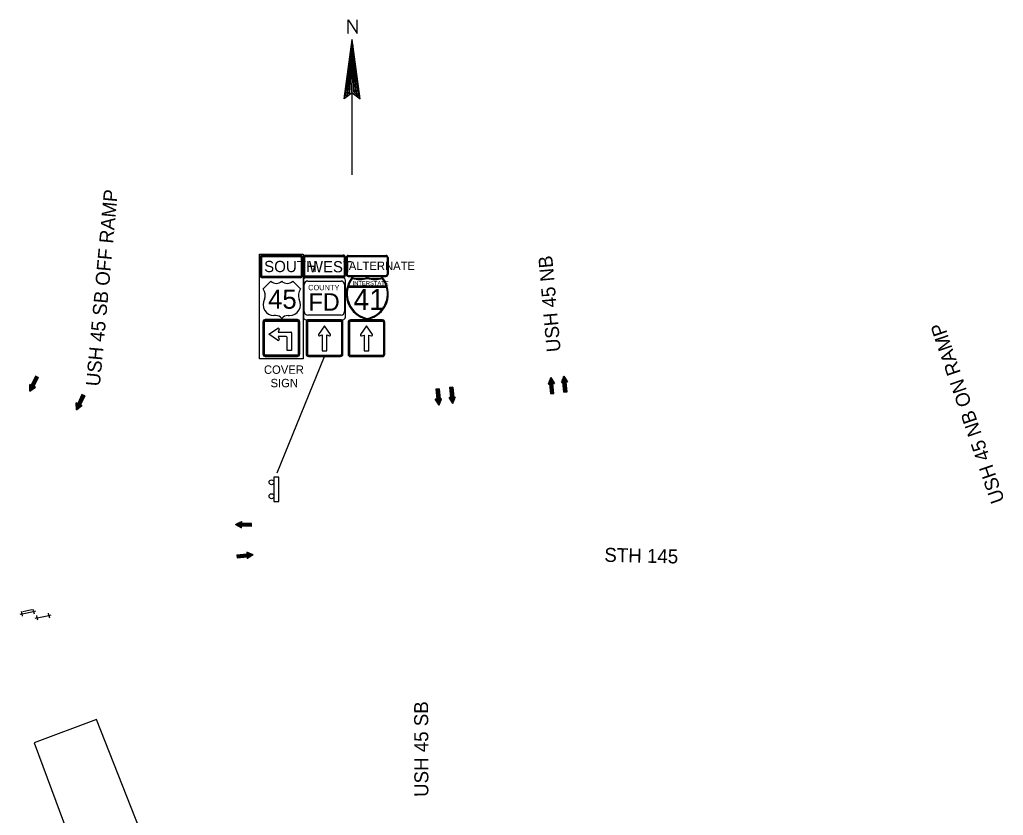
# Model space of a CAD drawing. Extents: x 358662 to 361839, y 132407 to 133741.
# Drawn here: x 361136 to 361839, y 133159 to 133727 of the extents above; entities that cross this region are included whole.
import ezdxf

# ---------------------------------------------------------------- set-up
doc = ezdxf.new("R2010")
doc.units = 0
for name, color, linetype in [('E_BLD_Dash', 7, 'Continuous'), ('E_BLD_Footing', 7, 'Continuous'), ('E_WTR_Wetland', 7, 'Continuous'), ('P_FTMS_LaneLbl', 7, 'Continuous')]:
    doc.layers.add(name, color=color, linetype=linetype)

msp = doc.modelspace()

# ---------------------------------------------------------------- linework, layer by layer
at = {"layer": 'E_BLD_Dash'}
for p, q in [((361137.32, 133302.53), (361135.66, 133302.17)), ((361137.32, 133302.53), (361136.96, 133304.19)), ((361137.32, 133302.53), (361145.63, 133304.32)), ((361137.68, 133300.87), (361137.32, 133302.53)), ((361137.94, 133304.4), (361144.29, 133305.77)), ((361145.63, 133304.32), (361145.27, 133305.99)), ((361145.63, 133304.32), (361147.29, 133304.68)), ((361145.63, 133304.32), (361145.98, 133302.66)), ((361148.26, 133299.68), (361146.6, 133299.32)), ((361148.26, 133299.68), (361147.9, 133301.34)), ((361148.26, 133299.68), (361156.57, 133301.48)), ((361148.62, 133298.02), (361148.26, 133299.68)), ((361156.57, 133301.48), (361156.21, 133303.14)), ((361156.57, 133301.48), (361158.23, 133301.84)), ((361156.57, 133301.48), (361156.93, 133299.82))]:
    msp.add_line(p, q, dxfattribs=at)
msp.add_lwpolyline([(361145.9, 133210.4), (361246.12, 132941.02), (361294.54, 132769.14), (361334.5, 132574.47), (361355.34, 132406.97), (361400.51, 132412.18), (361383.14, 132580.56), (361355.68, 132735.56), (361320.44, 132874.11), (361292.28, 132968.83), (361190.63, 133227.12)], close=True, dxfattribs=at)
at = {"layer": 'E_BLD_Footing'}
for p, q in [((361147.31, 133472.38), (361142.96, 133463.21)), ((361147.72, 133472.19), (361142.99, 133462.23)), ((361148.12, 133472), (361143.35, 133461.93)), ((361146.9, 133472.58), (361143.85, 133466.14)), ((361148.53, 133471.8), (361144.14, 133462.54)), ((361148.94, 133471.61), (361145.88, 133465.18)), ((361148.94, 133471.61), (361146.9, 133472.58)), ((361147.92, 133472.09), (361147.92, 133472.09)), ((361515.16, 133471.47), (361513.36, 133466.89)), ((361514.03, 133466.97), (361513.91, 133468.28)), ((361514.48, 133467.02), (361514.27, 133469.21)), ((361515.6, 133459.94), (361514.64, 133470.14)), ((361516.05, 133459.98), (361515, 133471.07)), ((361515.16, 133471.47), (361517.84, 133467.31)), ((361516.49, 133460.02), (361515.46, 133471)), ((361516.94, 133460.07), (361515.99, 133470.18)), ((361516.72, 133467.23), (361516.52, 133469.36)), ((361517.17, 133467.27), (361517.05, 133468.54)), ((361524.51, 133472.59), (361522.72, 133468.01)), ((361522.72, 133468.01), (361527.2, 133468.43)), ((361522.94, 133468.05), (361522.9, 133468.47)), ((361523.39, 133468.09), (361523.27, 133469.4)), ((361523.84, 133468.14), (361523.63, 133470.33)), ((361524.51, 133461.02), (361523.84, 133468.11)), ((361524.95, 133461.06), (361523.99, 133471.26)), ((361525.4, 133461.1), (361524.36, 133472.19)), ((361524.51, 133472.59), (361527.2, 133468.43)), ((361525.85, 133461.15), (361524.82, 133472.12)), ((361526.3, 133461.19), (361525.35, 133471.3)), ((361526.08, 133468.35), (361525.88, 133470.48)), ((361526.75, 133461.23), (361526.08, 133468.32)), ((361526.52, 133468.39), (361526.41, 133469.66)), ((361526.97, 133468.43), (361526.93, 133468.84)), ((361146.9, 133464.69), (361142.83, 133466.62)), ((361143.01, 133461.67), (361142.83, 133466.62)), ((361143.03, 133466.5), (361142.85, 133466.13)), ((361143.43, 133466.31), (361142.89, 133465.16)), ((361143.84, 133466.12), (361142.92, 133464.18)), ((361143.01, 133461.67), (361146.9, 133464.69)), ((361145.87, 133465.15), (361144.93, 133463.16)), ((361146.28, 133464.96), (361145.72, 133463.77)), ((361146.69, 133464.77), (361146.5, 133464.38)), ((361435.35, 133463.36), (361433.11, 133463.15)), ((361433.11, 133463.15), (361433.78, 133456.05)), ((361433.56, 133463.19), (361434.51, 133453.08)), ((361434, 133463.23), (361435.04, 133452.26)), ((361434.23, 133463.25), (361434.23, 133463.25)), ((361434.45, 133463.27), (361435.5, 133452.18)), ((361434.9, 133463.31), (361435.86, 133453.11)), ((361435.35, 133463.36), (361436.02, 133456.27)), ((361445.13, 133464.56), (361442.89, 133464.34)), ((361442.89, 133464.34), (361443.56, 133457.25)), ((361443.34, 133464.39), (361444.29, 133454.28)), ((361443.79, 133464.43), (361444.82, 133453.46)), ((361444.01, 133464.45), (361444.01, 133464.45)), ((361444.24, 133464.47), (361445.28, 133453.38)), ((361444.69, 133464.51), (361445.65, 133454.31)), ((361445.13, 133464.56), (361445.8, 133457.47)), ((361513.36, 133466.89), (361517.84, 133467.31)), ((361513.58, 133466.93), (361513.54, 133467.35)), ((361515.15, 133459.9), (361514.48, 133466.99)), ((361517.39, 133460.11), (361516.72, 133467.2)), ((361517.62, 133467.31), (361517.58, 133467.72)), ((361524.51, 133461.02), (361526.75, 133461.23)), ((361525.63, 133461.12), (361525.63, 133461.12)), ((361180.6, 133459.12), (361176.25, 133449.95)), ((361181.01, 133458.93), (361176.28, 133448.97)), ((361181.41, 133458.74), (361176.64, 133448.67)), ((361180.19, 133459.32), (361177.14, 133452.88)), ((361181.82, 133458.55), (361177.43, 133449.29)), ((361182.23, 133458.35), (361179.17, 133451.92)), ((361182.23, 133458.35), (361180.19, 133459.32)), ((361181.21, 133458.84), (361181.21, 133458.84)), ((361437.14, 133456.37), (361432.66, 133455.95)), ((361435.34, 133451.79), (361432.66, 133455.95)), ((361432.88, 133455.94), (361432.92, 133455.54)), ((361433.33, 133455.99), (361433.45, 133454.72)), ((361433.78, 133456.03), (361433.98, 133453.9)), ((361435.34, 133451.79), (361437.14, 133456.37)), ((361436.02, 133456.24), (361436.23, 133454.04)), ((361436.47, 133456.28), (361436.59, 133454.97)), ((361436.91, 133456.32), (361436.95, 133455.9)), ((361446.92, 133457.57), (361442.44, 133457.15)), ((361445.13, 133452.99), (361442.44, 133457.15)), ((361442.67, 133457.14), (361442.71, 133456.73)), ((361443.12, 133457.19), (361443.24, 133455.92)), ((361443.56, 133457.23), (361443.76, 133455.1)), ((361445.13, 133452.99), (361446.92, 133457.57)), ((361445.8, 133457.44), (361446.01, 133455.24)), ((361446.25, 133457.48), (361446.38, 133456.17)), ((361446.7, 133457.52), (361446.74, 133457.1)), ((361515.15, 133459.9), (361517.39, 133460.11)), ((361516.27, 133460), (361516.27, 133460)), ((361180.19, 133451.43), (361176.12, 133453.36)), ((361176.3, 133448.41), (361176.12, 133453.36)), ((361176.32, 133453.24), (361176.14, 133452.87)), ((361176.72, 133453.05), (361176.18, 133451.9)), ((361177.13, 133452.86), (361176.21, 133450.92)), ((361176.3, 133448.41), (361180.19, 133451.43)), ((361179.16, 133451.89), (361178.22, 133449.9)), ((361179.57, 133451.7), (361179.01, 133450.51)), ((361179.98, 133451.51), (361179.79, 133451.13)), ((361289.81, 133366.58), (361294.31, 133368.66)), ((361289.81, 133366.58), (361294.1, 133364.17)), ((361301.31, 133365.86), (361290.18, 133366.38)), ((361301.33, 133366.31), (361290.32, 133366.82)), ((361301.29, 133365.41), (361291.05, 133365.88)), ((361301.35, 133366.76), (361291.21, 133367.23)), ((361294.13, 133365.29), (361291.92, 133365.39)), ((361294.23, 133367.54), (361292.09, 133367.64)), ((361294.11, 133364.84), (361292.79, 133364.9)), ((361294.25, 133367.99), (361292.98, 133368.05)), ((361294.08, 133364.39), (361293.66, 133364.41)), ((361294.27, 133368.44), (361293.86, 133368.46)), ((361294.1, 133364.17), (361294.31, 133368.66)), ((361301.27, 133364.96), (361294.15, 133365.29)), ((361301.37, 133367.21), (361294.26, 133367.54)), ((361301.27, 133364.96), (361301.37, 133367.21)), ((361301.32, 133366.08), (361301.32, 133366.08)), ((361290.87, 133344.91), (361297.96, 133345.51)), ((361290.87, 133344.91), (361291.06, 133342.67)), ((361290.9, 133344.46), (361301.12, 133345.33)), ((361290.94, 133344.02), (361302.04, 133344.96)), ((361290.96, 133343.79), (361290.96, 133343.79)), ((361290.98, 133343.57), (361301.96, 133344.5)), ((361291.02, 133343.12), (361301.14, 133343.98)), ((361291.06, 133342.67), (361298.15, 133343.27)), ((361302.44, 133344.8), (361297.87, 133346.63)), ((361297.87, 133346.63), (361298.25, 133342.15)), ((361297.91, 133346.41), (361298.33, 133346.45)), ((361297.95, 133345.96), (361299.26, 133346.07)), ((361297.99, 133345.52), (361300.19, 133345.7)), ((361298.18, 133343.27), (361300.31, 133343.45)), ((361298.22, 133342.83), (361299.49, 133342.93)), ((361302.44, 133344.8), (361298.25, 133342.15)), ((361298.26, 133342.38), (361298.66, 133342.41))]:
    msp.add_line(p, q, dxfattribs=at)
at = {"layer": 'E_WTR_Wetland'}
for p, q in [((361307.51, 133557.37), (361307.51, 133544.31)), ((361307.88, 133557.37), (361307.88, 133544.31)), ((361308.39, 133557.37), (361308.39, 133544.31)), ((361308.99, 133558.88), (361336.15, 133558.88)), ((361309.01, 133558.5), (361336.15, 133558.5)), ((361309.01, 133558), (361336.15, 133558)), ((361336.78, 133557.37), (361336.78, 133544.31)), ((361337.28, 133557.37), (361337.28, 133544.31)), ((361337.66, 133557.37), (361337.66, 133544.31)), ((361338.32, 133557.49), (361338.32, 133544.49)), ((361338.69, 133557.49), (361338.69, 133544.49)), ((361339.19, 133557.49), (361339.19, 133544.49)), ((361339.8, 133558.99), (361366.82, 133558.99)), ((361339.82, 133558.62), (361366.82, 133558.62)), ((361339.82, 133558.12), (361366.82, 133558.12)), ((361367.44, 133557.49), (361367.44, 133544.49)), ((361367.94, 133557.49), (361367.94, 133544.49)), ((361368.32, 133557.49), (361368.32, 133544.49)), ((361368.88, 133557.31), (361368.88, 133545.31)), ((361369.26, 133557.31), (361369.26, 133545.31)), ((361369.63, 133557.31), (361369.63, 133545.31)), ((361370.38, 133558.81), (361397.38, 133558.81)), ((361370.38, 133558.43), (361397.38, 133558.43)), ((361370.38, 133558.06), (361397.38, 133558.06)), ((361398.13, 133557.31), (361398.13, 133545.31)), ((361398.51, 133557.31), (361398.51, 133545.31)), ((361398.88, 133557.31), (361398.88, 133545.31)), ((361336.15, 133543.68), (361309.01, 133543.68)), ((361336.15, 133543.18), (361309.01, 133543.18)), ((361336.15, 133542.8), (361309.01, 133542.8)), ((361315.14, 133540.38), (361309.57, 133534.82)), ((361336.31, 133534.82), (361330.74, 133540.38)), ((361338.4, 133540.99), (361338.4, 133514.74)), ((361366.82, 133543.87), (361339.82, 133543.87)), ((361366.82, 133543.37), (361339.82, 133543.37)), ((361366.82, 133542.99), (361339.82, 133542.99)), ((361366.52, 133542.86), (361340.27, 133542.86)), ((361341.52, 133540.52), (361365.27, 133540.52)), ((361368.4, 133514.74), (361368.4, 133540.99)), ((361370.38, 133544.56), (361397.38, 133544.56)), ((361370.38, 133544.18), (361397.38, 133544.18)), ((361370.38, 133543.81), (361397.38, 133543.81)), ((361339.02, 133518.64), (361339.02, 133538.02)), ((361367.77, 133538.02), (361367.77, 133518.64)), ((361370.33, 133536.14), (361397.81, 133536.14)), ((361397.63, 133536.77), (361370.51, 133536.77)), ((361339.02, 133518.64), (361339.02, 133518.64)), ((361309.52, 133511.27), (361309.52, 133488.3)), ((361309.96, 133488.3), (361309.96, 133511.27)), ((361310.51, 133488.3), (361310.51, 133511.27)), ((361334.13, 133512.91), (361311.16, 133512.91)), ((361311.16, 133512.47), (361334.13, 133512.47)), ((361311.16, 133511.92), (361334.13, 133511.92)), ((361318.48, 133515.88), (361317.37, 133515.88)), ((361327.39, 133515.88), (361328.51, 133515.88)), ((361334.79, 133488.3), (361334.79, 133511.27)), ((361335.34, 133488.3), (361335.34, 133511.27)), ((361335.77, 133488.3), (361335.77, 133511.27)), ((361340.27, 133512.86), (361366.52, 133512.86)), ((361340.34, 133511.17), (361340.34, 133488.21)), ((361340.78, 133511.17), (361340.78, 133488.21)), ((361341.32, 133511.17), (361341.32, 133488.21)), ((361365.27, 133516.14), (361341.52, 133516.14)), ((361364.95, 133512.81), (361341.98, 133512.81)), ((361341.98, 133512.38), (361364.95, 133512.38)), ((361341.98, 133511.83), (361364.95, 133511.83)), ((361365.61, 133511.17), (361365.61, 133488.21)), ((361366.15, 133511.17), (361366.15, 133488.21)), ((361366.59, 133488.21), (361366.59, 133511.17)), ((361370.34, 133511.05), (361370.34, 133488.08)), ((361370.78, 133511.05), (361370.78, 133488.08)), ((361371.32, 133511.05), (361371.32, 133488.08)), ((361394.95, 133512.69), (361371.98, 133512.69)), ((361371.98, 133512.26), (361394.95, 133512.26)), ((361371.98, 133511.71), (361394.95, 133511.71)), ((361395.61, 133511.05), (361395.61, 133488.08)), ((361396.15, 133511.05), (361396.15, 133488.08)), ((361396.59, 133488.08), (361396.59, 133511.05)), ((361313.79, 133502.41), (361319.98, 133506.67)), ((361320.98, 133505.94), (361320.41, 133504.05)), ((361320.41, 133504.05), (361329.32, 133504.05)), ((361329.98, 133503.39), (361329.98, 133490.92)), ((361353.47, 133508.55), (361349.21, 133502.36)), ((361357.72, 133502.36), (361353.47, 133508.55)), ((361383.46, 133508.43), (361379.21, 133502.24)), ((361387.72, 133502.24), (361383.46, 133508.43)), ((361319.98, 133498.15), (361313.79, 133502.41)), ((361326.15, 133500.77), (361320.41, 133500.77)), ((361320.41, 133500.77), (361320.98, 133498.88)), ((361326.69, 133490.92), (361326.69, 133500.22)), ((361349.94, 133501.36), (361351.82, 133501.93)), ((361351.82, 133501.93), (361351.82, 133490.72)), ((361355.11, 133490.72), (361355.11, 133501.93)), ((361355.11, 133501.93), (361356.99, 133501.36)), ((361379.94, 133501.24), (361381.82, 133501.81)), ((361381.82, 133501.81), (361381.82, 133490.6)), ((361385.11, 133490.6), (361385.11, 133501.81)), ((361385.11, 133501.81), (361386.99, 133501.24)), ((361329.98, 133490.92), (361326.69, 133490.92)), ((361351.82, 133490.72), (361355.11, 133490.72)), ((361381.82, 133490.6), (361385.11, 133490.6)), ((361311.16, 133487.64), (361334.13, 133487.64)), ((361311.16, 133487.09), (361334.13, 133487.09)), ((361311.16, 133486.66), (361334.13, 133486.66)), ((361341.98, 133487.55), (361364.95, 133487.55)), ((361341.98, 133487), (361364.95, 133487)), ((361341.98, 133486.56), (361364.95, 133486.56)), ((361371.98, 133487.43), (361394.95, 133487.43)), ((361371.98, 133486.88), (361394.95, 133486.88)), ((361371.98, 133486.44), (361394.95, 133486.44))]:
    msp.add_line(p, q, dxfattribs=at)
msp.add_lwpolyline([(361317.34, 133382.92), (361320.84, 133382.92), (361320.84, 133400.42), (361317.34, 133400.42)], close=True, dxfattribs=at)
for centre in [(361315.59, 133396.67), (361315.59, 133386.67)]:
    msp.add_circle(centre, 1.75, dxfattribs=at)
for centre, radius, start, end in [((361309.01, 133557.37), 1.51, 90.76565, 180), ((361309.01, 133557.37), 1.13, 90, 180), ((361309.01, 133557.37), 0.628, 90, 180), ((361336.15, 133557.37), 1.51, 0, 90), ((361336.15, 133557.37), 1.13, 0, 90), ((361336.15, 133557.37), 0.628, 0, 90), ((361339.82, 133557.49), 1.5, 90.76565, 180), ((361339.82, 133557.49), 1.12, 90, 180), ((361339.82, 133557.49), 0.625, 90, 180), ((361366.82, 133557.49), 1.5, 0, 90), ((361366.82, 133557.49), 1.12, 0, 90), ((361366.82, 133557.49), 0.625, 0, 90), ((361370.38, 133557.31), 1.5, 90, 180), ((361370.38, 133557.31), 1.13, 90, 180), ((361370.38, 133557.31), 0.75, 90, 180), ((361397.38, 133557.31), 1.5, 0, 90), ((361397.38, 133557.31), 1.13, 0, 90), ((361397.38, 133557.31), 0.75, 0, 90), ((361370.38, 133545.31), 1.5, 180, 270), ((361370.38, 133545.31), 1.13, 180, 270), ((361370.38, 133545.31), 0.75, 180, 270), ((361397.38, 133545.31), 1.5, 270, 360), ((361397.38, 133545.31), 1.13, 270, 360), ((361397.38, 133545.31), 0.75, 270, 360), ((361309.01, 133544.31), 1.51, 180, 270), ((361309.01, 133544.31), 1.13, 180, 270), ((361309.01, 133544.31), 0.628, 180, 270), ((361319.04, 133544.36), 5.57, 225.57283, 314.42717), ((361326.84, 133544.36), 5.57, 225.57283, 314.42717), ((361336.15, 133544.31), 1.13, 270, 360), ((361336.15, 133544.31), 0.628, 270, 360), ((361336.15, 133544.31), 1.51, 270, 360), ((361339.82, 133544.49), 1.5, 180, 270), ((361340.27, 133540.99), 1.87, 90, 180), ((361339.82, 133544.49), 1.12, 180, 270), ((361341.52, 133538.02), 2.5, 90, 180), ((361339.82, 133544.49), 0.625, 180, 270), ((361365.27, 133538.02), 2.5, 0, 90), ((361366.52, 133540.99), 1.87, 0, 90), ((361366.82, 133544.49), 1.12, 270, 360), ((361366.82, 133544.49), 0.625, 270, 360), ((361366.82, 133544.49), 1.5, 270, 360), ((361387.82, 133531.39), 18.75, 141.66896, 258.46304), ((361387.82, 133531.39), 18.12, 143.00407, 162.74499), ((361378.59, 133560.95), 18.75, 253.00398, 286.99096), ((361378.59, 133560.95), 19.37, 254.28765, 286.42705), ((361380.32, 133531.39), 18.75, 281.53696, 38.33104), ((361389.55, 133560.95), 18.75, 253.00904, 286.99602), ((361389.55, 133560.95), 19.37, 253.57295, 285.71235), ((361380.32, 133531.39), 18.12, 17.25501, 36.99593), ((361303.26, 133530.24), 7.8, 338.8697, 35.95201), ((361342.63, 133530.26), 7.8, 144.26805, 203.14107), ((361387.82, 133531.39), 18.12, 164.80279, 258.05946), ((361380.32, 133531.39), 18.12, 281.94054, 15.19721), ((361317.37, 133523.68), 7.8, 151.25191, 270.00007), ((361328.51, 133523.68), 7.8, 269.99993, 26.84655), ((361341.52, 133518.64), 2.5, 180, 270), ((361365.27, 133518.64), 2.5, 270, 0), ((361311.16, 133511.27), 1.64, 90, 180), ((361311.16, 133511.27), 1.2, 90, 180), ((361311.16, 133511.27), 0.656, 90, 180), ((361318.45, 133510.24), 5.64, 37.21219, 89.65771), ((361327.43, 133510.24), 5.64, 90.34229, 142.78781), ((361334.13, 133511.27), 1.64, 0, 90), ((361334.13, 133511.27), 1.2, 0, 90), ((361334.13, 133511.27), 0.656, 0, 90), ((361340.27, 133514.74), 1.87, 180, 270), ((361341.98, 133511.17), 1.64, 90, 180), ((361341.98, 133511.17), 1.2, 90, 180), ((361341.98, 133511.17), 0.656, 90, 180), ((361364.95, 133511.17), 1.64, 60.60346, 90), ((361364.95, 133511.17), 1.64, 0, 90), ((361364.95, 133511.17), 1.2, 0, 90), ((361364.95, 133511.17), 0.656, 0, 90), ((361366.52, 133514.74), 1.87, 270, 0), ((361371.98, 133511.05), 1.64, 90, 180), ((361371.98, 133511.05), 1.2, 90, 180), ((361371.98, 133511.05), 0.656, 90, 180), ((361394.95, 133511.05), 1.64, 60.60346, 90), ((361394.95, 133511.05), 1.64, 0, 90), ((361394.95, 133511.05), 1.2, 0, 90), ((361394.95, 133511.05), 0.656, 0, 90), ((361320.35, 133506.13), 0.656, 343.1974, 124.52967), ((361329.32, 133503.39), 0.656, 0, 90), ((361320.35, 133498.69), 0.656, 235.47033, 16.8026), ((361326.15, 133500.22), 0.547, 0, 90), ((361349.75, 133501.99), 0.656, 145.47033, 286.8026), ((361357.18, 133501.99), 0.656, 253.1974, 34.52967), ((361379.75, 133501.87), 0.656, 145.47033, 286.8026), ((361387.18, 133501.87), 0.656, 253.1974, 34.52967), ((361311.16, 133488.3), 1.64, 180, 270), ((361311.16, 133488.3), 1.2, 180, 270), ((361311.16, 133488.3), 0.656, 180, 270), ((361334.13, 133488.3), 0.656, 270, 0), ((361334.13, 133488.3), 1.2, 270, 360), ((361334.13, 133488.3), 1.64, 270, 0), ((361341.98, 133488.21), 1.64, 180, 270), ((361341.98, 133488.21), 1.2, 180, 270), ((361341.98, 133488.21), 0.656, 180, 270), ((361364.95, 133488.21), 1.2, 270, 0), ((361364.95, 133488.21), 1.64, 270, 0), ((361364.95, 133488.21), 0.656, 270, 0), ((361371.98, 133488.08), 1.64, 180, 270), ((361371.98, 133488.08), 1.2, 180, 270), ((361371.98, 133488.08), 0.656, 180, 270), ((361394.95, 133488.08), 1.2, 270, 0), ((361394.95, 133488.08), 1.64, 270, 0), ((361394.95, 133488.08), 0.656, 270, 0)]:
    msp.add_arc(centre, radius, start, end, dxfattribs=at)
at = {"layer": 'P_FTMS_LaneLbl'}
for p, q in [((361370.58, 133727.07), (361370.58, 133727.07)), ((361370.5, 133717.23), (361370.5, 133717.23)), ((361373.2, 133713.07), (361373.08, 133712.75)), ((361373.2, 133713.07), (361373.2, 133713.07)), ((361368.59, 133679.14), (361368.59, 133679.14)), ((361368.83, 133679.5), (361368.83, 133679.5)), ((361377.57, 133679.5), (361377.57, 133679.5)), ((361377.8, 133679.14), (361377.8, 133679.14)), ((361373.2, 133616.32), (361373.2, 133675)), ((361373.2, 133616.32), (361373.2, 133674.98)), ((361367.44, 133670.66), (361367.44, 133670.66)), ((361367.73, 133671.11), (361367.73, 133671.11)), ((361378.66, 133671.11), (361378.66, 133671.11)), ((361378.95, 133670.66), (361378.95, 133670.66)), ((361319.73, 133403.38), (361353.47, 133486.56))]:
    msp.add_line(p, q, dxfattribs=at)
for points in [[(361370.48, 133717.47), (361370.48, 133727.31), (361376.91, 133717.47), (361376.91, 133727.31)], [(361373.2, 133675), (361367.44, 133670.66), (361373.2, 133713.07)], [(361368.23, 133671.98), (361373.21, 133710.2), (361369.11, 133672.61), (361370.02, 133673.37), (361373.17, 133706.44), (361370.81, 133674.08), (361371.69, 133674.91), (361373.17, 133701.7), (361372.68, 133675.46)], [(361373.2, 133675), (361378.95, 133670.66), (361373.2, 133713.07)], [(361378.34, 133671.98), (361373.36, 133710.2), (361377.46, 133672.61), (361376.55, 133673.37), (361373.4, 133706.44), (361375.75, 133674.08), (361374.88, 133674.91), (361373.4, 133701.7), (361373.89, 133675.46)]]:
    msp.add_lwpolyline(points, dxfattribs=at)
msp.add_lwpolyline([(361307.11, 133559.77), (361338.14, 133559.77), (361338.14, 133484.89), (361307.11, 133484.89)], close=True, dxfattribs=at)

# ---------------------------------------------------------------- texts
at = {"layer": 'E_WTR_Wetland'}
for s, height, p in [('SOUTH', 8.04, (361310.35, 133546.87)), ('WEST', 8, (361342.28, 133546.74)), ('ALTERNATE', 6, (361370.85, 133548.38)), ('INTERSTATE', 3, (361373.56, 133537.47)), ('45', 13.698, (361313.19, 133520.68)), ('COUNTY', 3.833, (361341.77, 133533.91)), ('FD', 12.5, (361342.06, 133519.28)), ('41', 15, (361374.24, 133519.82))]:
    msp.add_text(s, height=height, dxfattribs=at).set_placement(p)
at = {"layer": 'P_FTMS_LaneLbl'}
for s, rotation, p in [('USH 45 SB OFF RAMP', 84.70788, (361192.92, 133464.92)), ('USH 45 NB', 95.11438, (361522.29, 133490.2)), ('USH 45 NB ON RAMP', 108.9056, (361839.57, 133383.56)), ('STH 145', 358.65017, (361553.33, 133339.86)), ('USH 45 SB', 90.15807, (361427.71, 133171.77))]:
    msp.add_text(s, height=10, rotation=rotation, dxfattribs=at).set_placement(p)
for s, p in [('COVER', (361310.21, 133474.17)), ('SIGN', (361314.93, 133464.57))]:
    msp.add_text(s, height=6, dxfattribs=at).set_placement(p)

doc.saveas('drawing.dxf')
